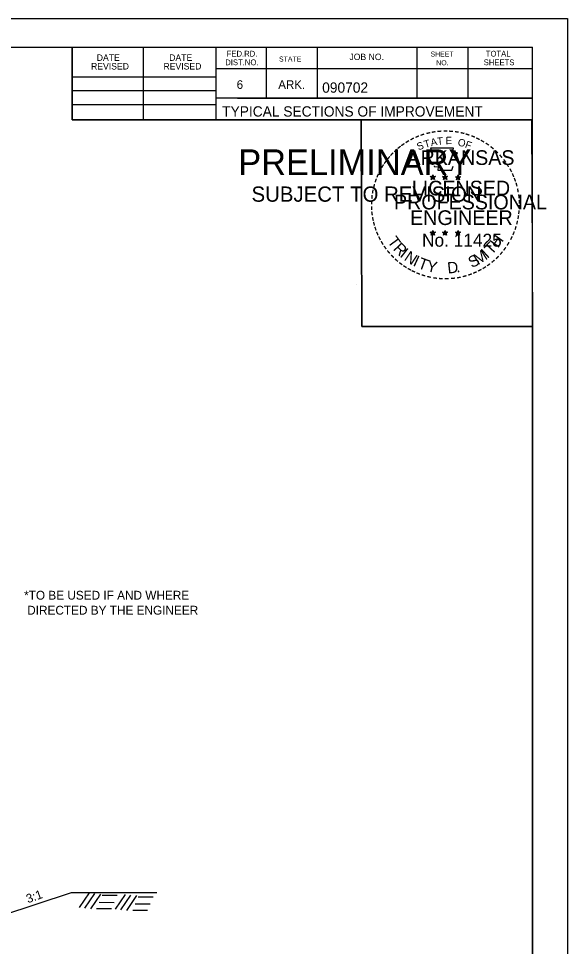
# Model space of a CAD drawing. Extents: x 1371763 to 1372860, y 385599 to 385872.
# Drawn here: x 1372129.4 to 1372166.7, y 385642.1 to 385705.3 of the extents above; entities that cross this region are included whole.
import ezdxf

# ---------------------------------------------------------------- set-up
doc = ezdxf.new("R2010")
doc.units = 0
for name, color, linetype in [('R_Draft', 7, 'Continuous'), ('R_Fin Surface', 7, 'Continuous'), ('R_No Plot', 7, 'Continuous')]:
    doc.layers.add(name, color=color, linetype=linetype)

msp = doc.modelspace()

# ---------------------------------------------------------------- linework, layer by layer
at = {"layer": 'R_Draft'}
for p, q in [((1372133.536, 385644.735), (1372134.212, 385645.737)), ((1372133.895, 385644.694), (1372134.571, 385645.695)), ((1372134.295, 385644.652), (1372134.971, 385645.653)), ((1372135.989, 385644.627), (1372136.665, 385645.628)), ((1372134.871, 385645.094), (1372135.889, 385645.086)), ((1372135.071, 385645.578), (1372136.089, 385645.57)), ((1372136.348, 385644.585), (1372137.023, 385645.587)), ((1372136.748, 385644.543), (1372137.424, 385645.545)), ((1372137.324, 385644.986), (1372138.342, 385644.977)), ((1372137.524, 385645.47), (1372138.542, 385645.462)), ((1372134.696, 385644.669), (1372135.714, 385644.66)), ((1372137.148, 385644.56), (1372138.166, 385644.552))]:
    msp.add_line(p, q, dxfattribs=at)
at = {"layer": 'R_Fin Surface'}
for p, q in [((1372128.239, 385644.185), (1372132.983, 385645.766)), ((1372132.983, 385645.766), (1372138.8, 385645.766))]:
    msp.add_line(p, q, dxfattribs=at)
at = {"layer": 'R_No Plot'}
for p, q in [((1372000.064, 385705.254), (1372166.73, 385705.254)), ((1372006.264, 385703.307), (1372164.354, 385703.307)), ((1372133.034, 385698.367), (1372133.034, 385703.307)), ((1372137.874, 385698.367), (1372137.874, 385703.307)), ((1372142.804, 385703.307), (1372142.804, 385698.367)), ((1372146.224, 385703.307), (1372146.224, 385699.837)), ((1372149.694, 385703.307), (1372149.694, 385699.837)), ((1372156.484, 385703.307), (1372156.484, 385699.837)), ((1372159.954, 385703.307), (1372159.954, 385699.837)), ((1372164.354, 385600.577), (1372164.354, 385703.307)), ((1372164.354, 385701.837), (1372142.804, 385701.837)), ((1372164.354, 385701.847), (1372164.354, 385701.847)), ((1372133.034, 385701.297), (1372142.804, 385701.297)), ((1372133.034, 385700.367), (1372142.804, 385700.367)), ((1372133.034, 385699.397), (1372142.804, 385699.397)), ((1372164.354, 385699.837), (1372142.804, 385699.837)), ((1372144.284, 385699.837), (1372164.354, 385699.837)), ((1372164.354, 385698.367), (1372133.034, 385698.367)), ((1372157.397, 385694.494), (1372157.571, 385694.439)), ((1372157.397, 385694.494), (1372157.523, 385694.472)), ((1372157.397, 385694.494), (1372157.515, 385694.433)), ((1372157.463, 385694.29), (1372157.571, 385694.439)), ((1372157.463, 385694.29), (1372157.526, 385694.412)), ((1372157.463, 385694.29), (1372157.57, 385694.399)), ((1372157.571, 385694.621), (1372157.551, 385694.495)), ((1372157.678, 385694.29), (1372157.57, 385694.397)), ((1372157.571, 385694.439), (1372157.571, 385694.621)), ((1372157.571, 385694.621), (1372157.596, 385694.496)), ((1372157.745, 385694.494), (1372157.571, 385694.439)), ((1372157.678, 385694.29), (1372157.571, 385694.439)), ((1372157.745, 385694.494), (1372157.602, 385694.47)), ((1372157.678, 385694.29), (1372157.609, 385694.436)), ((1372157.745, 385694.494), (1372157.643, 385694.443)), ((1372158.232, 385694.494), (1372158.406, 385694.439)), ((1372158.232, 385694.494), (1372158.358, 385694.472)), ((1372158.232, 385694.494), (1372158.35, 385694.433)), ((1372158.298, 385694.29), (1372158.406, 385694.439)), ((1372158.298, 385694.29), (1372158.361, 385694.412)), ((1372158.298, 385694.29), (1372158.405, 385694.399)), ((1372158.406, 385694.621), (1372158.386, 385694.495)), ((1372158.513, 385694.29), (1372158.405, 385694.397)), ((1372158.406, 385694.439), (1372158.406, 385694.621)), ((1372158.406, 385694.621), (1372158.431, 385694.496)), ((1372158.58, 385694.494), (1372158.406, 385694.439)), ((1372158.513, 385694.29), (1372158.406, 385694.439)), ((1372158.58, 385694.494), (1372158.437, 385694.47)), ((1372158.513, 385694.29), (1372158.444, 385694.436)), ((1372158.58, 385694.494), (1372158.478, 385694.443)), ((1372159.114, 385694.488), (1372159.288, 385694.433)), ((1372159.114, 385694.488), (1372159.24, 385694.466)), ((1372159.114, 385694.488), (1372159.232, 385694.427)), ((1372159.18, 385694.284), (1372159.288, 385694.433)), ((1372159.18, 385694.284), (1372159.243, 385694.406)), ((1372159.18, 385694.284), (1372159.287, 385694.393)), ((1372159.288, 385694.615), (1372159.268, 385694.489)), ((1372159.395, 385694.284), (1372159.287, 385694.391)), ((1372159.288, 385694.433), (1372159.288, 385694.615)), ((1372159.288, 385694.615), (1372159.313, 385694.49)), ((1372159.462, 385694.488), (1372159.288, 385694.433)), ((1372159.395, 385694.284), (1372159.288, 385694.433)), ((1372159.462, 385694.488), (1372159.319, 385694.464)), ((1372159.395, 385694.284), (1372159.326, 385694.43)), ((1372159.462, 385694.488), (1372159.36, 385694.437)), ((1372157.395, 385690.708), (1372157.569, 385690.652)), ((1372157.395, 385690.708), (1372157.521, 385690.685)), ((1372157.395, 385690.708), (1372157.513, 385690.647)), ((1372157.461, 385690.504), (1372157.569, 385690.652)), ((1372157.461, 385690.504), (1372157.524, 385690.626)), ((1372157.461, 385690.504), (1372157.568, 385690.612)), ((1372157.569, 385690.835), (1372157.549, 385690.709)), ((1372157.676, 385690.504), (1372157.568, 385690.611)), ((1372157.569, 385690.652), (1372157.569, 385690.835)), ((1372157.569, 385690.835), (1372157.594, 385690.71)), ((1372157.743, 385690.708), (1372157.569, 385690.652)), ((1372157.676, 385690.504), (1372157.569, 385690.652)), ((1372157.743, 385690.708), (1372157.6, 385690.683)), ((1372157.676, 385690.504), (1372157.607, 385690.649)), ((1372157.743, 385690.708), (1372157.641, 385690.657)), ((1372158.229, 385690.708), (1372158.404, 385690.652)), ((1372158.229, 385690.708), (1372158.356, 385690.685)), ((1372158.229, 385690.708), (1372158.348, 385690.647)), ((1372158.296, 385690.504), (1372158.404, 385690.652)), ((1372158.296, 385690.504), (1372158.359, 385690.626)), ((1372158.296, 385690.504), (1372158.403, 385690.612)), ((1372158.404, 385690.835), (1372158.383, 385690.709)), ((1372158.51, 385690.504), (1372158.403, 385690.611)), ((1372158.404, 385690.652), (1372158.404, 385690.835)), ((1372158.404, 385690.835), (1372158.428, 385690.71)), ((1372158.577, 385690.708), (1372158.404, 385690.652)), ((1372158.51, 385690.504), (1372158.404, 385690.652)), ((1372158.577, 385690.708), (1372158.434, 385690.683)), ((1372158.51, 385690.504), (1372158.442, 385690.649)), ((1372158.577, 385690.708), (1372158.475, 385690.657)), ((1372159.113, 385690.703), (1372159.287, 385690.647)), ((1372159.113, 385690.703), (1372159.239, 385690.68)), ((1372159.113, 385690.703), (1372159.231, 385690.642)), ((1372159.179, 385690.499), (1372159.287, 385690.647)), ((1372159.179, 385690.499), (1372159.242, 385690.621)), ((1372159.179, 385690.499), (1372159.286, 385690.607)), ((1372159.287, 385690.83), (1372159.267, 385690.704)), ((1372159.394, 385690.499), (1372159.286, 385690.606)), ((1372159.287, 385690.647), (1372159.287, 385690.83)), ((1372159.287, 385690.83), (1372159.312, 385690.705)), ((1372159.461, 385690.703), (1372159.287, 385690.647)), ((1372159.394, 385690.499), (1372159.287, 385690.647)), ((1372159.461, 385690.703), (1372159.318, 385690.678)), ((1372159.394, 385690.499), (1372159.325, 385690.644)), ((1372159.461, 385690.703), (1372159.359, 385690.652)), ((1372152.371, 385687.139), (1372152.371, 385687.139))]:
    msp.add_line(p, q, dxfattribs=at)
for points in [[(1372000.06, 385705.254), (1372166.73, 385705.254), (1372166.73, 385598.585), (1372000.06, 385598.585)], [(1372123.224, 385703.307), (1372133.034, 385703.307), (1372133.034, 385698.367), (1372141.09, 385698.367), (1372152.69, 385698.367), (1372152.75, 385684.288), (1372164.354, 385684.288), (1372164.354, 385600.577), (1372006.264, 385600.577), (1372006.264, 385703.307)], [(1372152.69, 385698.367), (1372164.294, 385698.367), (1372164.354, 385684.288), (1372152.75, 385684.288)]]:
    msp.add_lwpolyline(points, close=True, dxfattribs=at)
for points in [[(1372157.417, 385696.433), (1372157.552, 385696.02)], [(1372159.173, 385695.972), (1372159.244, 385696.114), (1372158.901, 385696.102), (1372158.975, 385696.433), (1372157.417, 385696.433)], [(1372157.663, 385695.222), (1372157.663, 385695.178), (1372157.945, 385695.169), (1372157.918, 385694.932), (1372158.853, 385694.932), (1372158.953, 385695.2)], [(1372157.571, 385694.621), (1372157.678, 385694.29), (1372157.397, 385694.494), (1372157.745, 385694.494), (1372157.463, 385694.29), (1372157.571, 385694.621)], [(1372158.406, 385694.621), (1372158.513, 385694.29), (1372158.232, 385694.494), (1372158.58, 385694.494), (1372158.298, 385694.29), (1372158.406, 385694.621)], [(1372159.288, 385694.615), (1372159.395, 385694.284), (1372159.114, 385694.488), (1372159.462, 385694.488), (1372159.18, 385694.284), (1372159.288, 385694.615)], [(1372157.569, 385690.835), (1372157.676, 385690.504), (1372157.395, 385690.708), (1372157.743, 385690.708), (1372157.461, 385690.504), (1372157.569, 385690.835)], [(1372158.404, 385690.835), (1372158.51, 385690.504), (1372158.229, 385690.708), (1372158.577, 385690.708), (1372158.296, 385690.504), (1372158.404, 385690.835)], [(1372159.287, 385690.83), (1372159.394, 385690.499), (1372159.113, 385690.703), (1372159.461, 385690.703), (1372159.179, 385690.499), (1372159.287, 385690.83)]]:
    msp.add_lwpolyline(points, dxfattribs=at)
for centre, radius in [((1372157.571, 385694.438), 0.0861), ((1372157.571, 385694.438), 0.0723), ((1372157.571, 385694.438), 0.0579), ((1372157.571, 385694.438), 0.0495), ((1372157.571, 385694.438), 0.0374), ((1372157.571, 385694.438), 0.0248), ((1372157.571, 385694.438), 0.0148), ((1372158.406, 385694.438), 0.0861), ((1372158.406, 385694.438), 0.0723), ((1372158.406, 385694.438), 0.0579), ((1372158.406, 385694.438), 0.0495), ((1372158.406, 385694.438), 0.0374), ((1372158.406, 385694.438), 0.0248), ((1372158.406, 385694.438), 0.0148), ((1372159.288, 385694.432), 0.0861), ((1372159.288, 385694.432), 0.0723), ((1372159.288, 385694.432), 0.0579), ((1372159.288, 385694.432), 0.0495), ((1372159.288, 385694.432), 0.0374), ((1372159.288, 385694.432), 0.0248), ((1372159.288, 385694.432), 0.0148), ((1372157.569, 385690.652), 0.0861), ((1372157.569, 385690.652), 0.0723), ((1372157.569, 385690.652), 0.0579), ((1372157.569, 385690.652), 0.0495), ((1372157.569, 385690.652), 0.0374), ((1372157.569, 385690.652), 0.0248), ((1372157.569, 385690.652), 0.0148), ((1372158.403, 385690.652), 0.0861), ((1372158.403, 385690.652), 0.0723), ((1372158.403, 385690.652), 0.0579), ((1372158.403, 385690.652), 0.0495), ((1372158.403, 385690.652), 0.0374), ((1372158.403, 385690.652), 0.0248), ((1372158.403, 385690.652), 0.0148), ((1372159.287, 385690.647), 0.0861), ((1372159.287, 385690.647), 0.0723), ((1372159.287, 385690.647), 0.0579), ((1372159.287, 385690.647), 0.0495), ((1372159.287, 385690.647), 0.0374), ((1372159.287, 385690.647), 0.0248), ((1372159.287, 385690.647), 0.0148)]:
    msp.add_circle(centre, radius, dxfattribs=at)

# ---------------------------------------------------------------- texts
at = {"layer": 'R_Draft'}
for s, rotation, p in [('*TO BE USED IF AND WHERE ', 360, (1372129.759, 385665.696)), ('DIRECTED BY THE ENGINEER', 360, (1372129.97, 385664.676)), ('3:1', 19.99783, (1372130.022, 385645.019))]:
    msp.add_text(s, height=0.6, rotation=rotation, dxfattribs=at).set_placement(p)
at = {"layer": 'R_No Plot'}
for s, height, p in [('DATE', 0.4396, (1372134.703, 385702.375)), ('DATE', 0.4396, (1372139.633, 385702.375)), ('DIST.NO.', 0.391, (1372143.444, 385702.077)), ('FED.RD.', 0.391, (1372143.544, 385702.667)), ('STATE', 0.342, (1372147.104, 385702.327)), ('JOB NO.', 0.4396, (1372151.894, 385702.427)), ('SHEET', 0.342, (1372157.414, 385702.667)), ('SHEETS', 0.391, (1372161.034, 385702.077)), ('TOTAL', 0.391, (1372161.174, 385702.667)), ('REVISED', 0.4396, (1372134.313, 385701.785)), ('REVISED', 0.4396, (1372139.243, 385701.785)), ('NO.', 0.342, (1372157.804, 385702.077)), ('6', 0.586, (1372144.224, 385700.467)), ('ARK.', 0.5861, (1372147.054, 385700.467)), ('090702', 0.7, (1372150.042, 385700.206)), ('TYPICAL SECTIONS OF IMPROVEMENT', 0.7, (1372143.236, 385698.582)), ('PRELIMINARY', 1.75, (1372144.33, 385694.598)), ('ARKANSAS', 1, (1372155.844, 385695.289)), ('DWB', 0.005, (1372144.703, 385695.523)), ('DWB', 0.005, (1372157.565, 385694.436)), ('DWB', 0.005, (1372158.4, 385694.436)), ('DWB', 0.005, (1372159.282, 385694.431)), ('SUBJECT TO REVISION', 1.03756, (1372145.234, 385692.784)), ('LICENSED', 1, (1372156.142, 385693.215)), ('PROFESSIONAL', 1, (1372154.931, 385692.263)), ('ENGINEER', 1, (1372156.024, 385691.2)), ('No. 11425', 0.8785, (1372156.838, 385689.725)), ('DWB', 0.005, (1372157.563, 385690.65)), ('DWB', 0.005, (1372158.397, 385690.65)), ('DWB', 0.005, (1372159.281, 385690.645))]:
    msp.add_text(s, height=height, dxfattribs=at).set_placement(p)
for s, height, rotation, p in [('-', 0.8, 19.17608, (1372156.791, 385696.997)), ('-', 0.8, 13.63015, (1372157.166, 385697.117)), ('-', 0.8, 10.21935, (1372157.505, 385697.198)), ('-', 0.8, 5.89682, (1372157.87, 385697.253)), ('-', 0.8, 0.18623, (1372158.256, 385697.289)), ('-', 0.8, 357.74304, (1372158.617, 385697.283)), ('-', 0.8, 352.16172, (1372158.989, 385697.255)), ('-', 0.8, 347.20489, (1372159.349, 385697.198)), ('-', 0.8, 342.3362, (1372159.666, 385697.12)), ('-', 0.8, 36.23174, (1372155.57, 385696.321)), ('-', 0.8, 34.06357, (1372155.859, 385696.519)), ('-', 0.8, 28.79182, (1372156.158, 385696.704)), ('-', 0.8, 24.30721, (1372156.474, 385696.862)), ('S', 0.5, 21.59401, (1372156.595, 385696.272)), ('T', 0.5, 16.4036, (1372157.052, 385696.438)), ('A', 0.5, 11.21318, (1372157.465, 385696.563)), ('T', 0.5, 6.02276, (1372157.889, 385696.646)), ('E', 0.5, 0.83234, (1372158.442, 385696.701)), ('O', 0.5, 350.4515, (1372159.244, 385696.596)), ('F', 0.5, 340.07066, (1372159.721, 385696.482)), ('-', 0.8, 337.85509, (1372160.034, 385697.009)), ('-', 0.8, 334.12109, (1372160.349, 385696.873)), ('-', 0.8, 329.64089, (1372160.639, 385696.732)), ('-', 0.8, 325.86266, (1372160.96, 385696.551)), ('-', 0.8, 48.42305, (1372154.892, 385695.685)), ('-', 0.8, 42.96224, (1372155.116, 385695.924)), ('-', 0.8, 38.95066, (1372155.332, 385696.132)), ('-', 0.8, 320.52971, (1372161.265, 385696.338)), ('-', 0.8, 315.57859, (1372161.565, 385696.094)), ('-', 0.8, 54.23247, (1372154.484, 385695.158)), ('-', 0.8, 50.61417, (1372154.69, 385695.442)), ('-', 0.8, 309.87973, (1372161.849, 385695.819)), ('-', 0.8, 306.65218, (1372162.112, 385695.518)), ('-', 0.8, 62.87135, (1372154.165, 385694.588)), ('-', 0.8, 58.07063, (1372154.321, 385694.895)), ('-', 0.7, 303.67529, (1372162.355, 385695.234)), ('-', 0.8, 299.66835, (1372162.514, 385694.931)), ('-', 0.8, 72.39447, (1372153.926, 385693.967)), ('-', 0.8, 67.77427, (1372154.035, 385694.282)), ('-', 0.8, 294.66279, (1372162.676, 385694.625)), ('-', 0.8, 290.57283, (1372162.805, 385694.336)), ('-', 0.8, 81.20126, (1372153.761, 385693.254)), ('-', 0.8, 75.46096, (1372153.827, 385693.61)), ('-', 0.8, 285.12326, (1372162.922, 385694.046)), ('-', 0.8, 280.54934, (1372163.022, 385693.675)), ('-', 0.8, 85.18634, (1372153.723, 385692.908)), ('-', 0.8, 276.59616, (1372163.103, 385693.291)), ('-', 0.8, 94.19588, (1372153.728, 385692.195)), ('-', 0.8, 89.06224, (1372153.711, 385692.558)), ('-', 0.8, 274.33011, (1372163.133, 385692.93)), ('-', 0.8, 269.94067, (1372163.15, 385692.614)), ('-', 0.8, 98.94793, (1372153.764, 385691.862)), ('-', 0.8, 101.71495, (1372153.832, 385691.495)), ('-', 0.8, 260.99529, (1372163.105, 385691.954)), ('-', 0.8, 263.5172, (1372163.14, 385692.281)), ('-', 0.8, 105.45785, (1372153.913, 385691.198)), ('-', 0.8, 109.08742, (1372154.02, 385690.882)), ('-', 0.8, 252.86809, (1372162.959, 385691.255)), ('-', 0.8, 255.7626, (1372163.05, 385691.615)), ('-', 0.8, 114.06432, (1372154.147, 385690.584)), ('T', 0.77, 306.04056, (1372154.449, 385690.071)), ('H', 0.77, 54.60883, (1372162.009, 385689.589)), ('-', 0.8, 247.88866, (1372162.848, 385690.919)), ('-', 0.8, 115.72885, (1372154.3, 385690.275)), ('-', 0.8, 120.44712, (1372154.478, 385689.982)), ('R', 0.77, 314.00497, (1372154.83, 385689.547)), ('T', 0.77, 46.64442, (1372161.564, 385689.118)), ('-', 0.8, 239.07125, (1372162.52, 385690.228)), ('-', 0.8, 244.61971, (1372162.717, 385690.604)), ('-', 0.8, 125.89344, (1372154.68, 385689.702)), ('-', 0.8, 130.71812, (1372154.911, 385689.426)), ('-', 0.8, 134.22381, (1372155.169, 385689.153)), ('I', 0.77, 321.96938, (1372155.28, 385689.081)), ('N', 0.77, 326.50021, (1372155.564, 385688.846)), ('M', 0.77, 32.65632, (1372160.641, 385688.455)), ('I', 0.77, 42.11359, (1372161.283, 385688.879)), ('-', 0.8, 231.25377, (1372162.104, 385689.619)), ('-', 0.8, 233.84524, (1372162.319, 385689.902)), ('-', 0.8, 138.93382, (1372155.432, 385688.921)), ('-', 0.8, 144.64634, (1372155.71, 385688.718)), ('I', 0.77, 335.36034, (1372156.168, 385688.453)), ('T', 0.77, 339.89117, (1372156.499, 385688.289)), ('Y', 0.77, 347.85558, (1372157.107, 385688.066)), ('D', 0.77, 6.39691, (1372158.6, 385687.887)), ('S', 0.77, 26.9312, (1372160.222, 385688.252)), ('-', 0.8, 215.73633, (1372161.329, 385688.846)), ('-', 0.8, 221.08509, (1372161.603, 385689.082)), ('-', 0.8, 225.76533, (1372161.864, 385689.337)), ('-', 0.8, 148.08978, (1372155.99, 385688.533)), ('-', 0.8, 151.57039, (1372156.28, 385688.37)), ('-', 0.8, 154.60019, (1372156.541, 385688.247)), ('-', 0.8, 158.56121, (1372156.853, 385688.12)), ('.', 0.77, 13.76417, (1372159.196, 385687.951)), ('-', 0.8, 204.25161, (1372160.471, 385688.32)), ('-', 0.8, 207.35684, (1372160.783, 385688.48)), ('-', 0.8, 212.24909, (1372161.062, 385688.653)), ('-', 0.8, 162.79826, (1372157.196, 385688.013)), ('-', 0.8, 167.55551, (1372157.554, 385687.931)), ('-', 0.8, 173.11546, (1372157.94, 385687.876)), ('-', 0.8, 176.51827, (1372158.314, 385687.85)), ('-', 0.8, 181.59176, (1372158.686, 385687.859)), ('-', 0.8, 185.81666, (1372159.09, 385687.897)), ('-', 0.8, 191.28576, (1372159.458, 385687.963)), ('-', 0.8, 195.47429, (1372159.823, 385688.063)), ('-', 0.8, 200.71842, (1372160.161, 385688.184))]:
    msp.add_text(s, height=height, rotation=rotation, dxfattribs=at).set_placement(p)

doc.saveas('drawing.dxf')
